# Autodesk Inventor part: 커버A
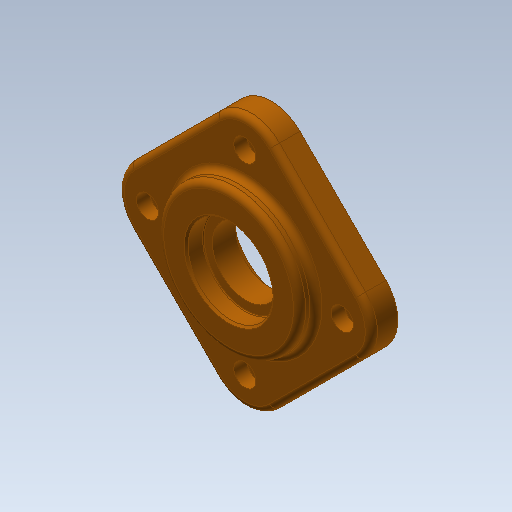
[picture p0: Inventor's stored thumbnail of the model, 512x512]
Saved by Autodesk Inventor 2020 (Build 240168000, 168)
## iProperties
Created: 2013-01
Part Number: 커버A
Document SubType Name: Modeling
Density: 1 g/cm^3
Material: 알루미늄 6061
Designer: mdu
Appearance: 주황색
Author: mdu
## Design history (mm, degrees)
sketch "스케치1"
  geometry: L1 (56.569, -14.142)-(14.142, -56.569) reference; L2 (-14.142, -56.569)-(-56.569, -14.142) reference; L3 (-56.569, 14.142)-(-14.142, 56.569) reference; L4 (14.142, 56.569)-(56.569, 14.142) reference; C1 r 31 at (0, 0) reference; A1 r 20 centre (0, -42.426) between (-14.142, -56.569) and (14.142, -56.569) reference; A2 r 20 centre (-42.426, 0) between (-56.569, 14.142) and (-56.569, -14.142) reference; A3 r 20 centre (0, 42.426) between (14.142, 56.569) and (-14.142, 56.569) reference; A4 r 20 centre (42.426, 0) between (56.569, -14.142) and (56.569, 14.142) reference; 1 further point
extrude "돌출1" new body sketch "스케치1" distance "d0" = 13; taper "d1" = 0 deg
sketch "스케치2"
  geometry: C1 r 35 at (0, 0); 1 further point
  constraints: 1 centre point, 1 coincident
  dimensions: "d2" = 70 diameter of C1
extrude "돌출2" join sketch "스케치2" distance "d3" = 8; taper "d4" = 0 deg
fillet "모깎기1" dims "d5" = 3
sketch "스케치3"
  geometry: C1 r 2.458 at (0, 48) reference; 1 further point
hole "구멍1" sketch "스케치3" at (0, 48) diameter "d6" = 6.6; stored, may be unused: countersink angle "d10" = 90 deg, drill point angle "d12" = 118 deg; dims "d7" = 6, "d8" = 11, "d9" = 6.5, "d11" = 8
hole "구멍2" diameter "d18" = 33; stored, may be unused: countersink angle "d22" = 90 deg, drill point angle "d24" = 118 deg; dims "d16" = 10, "d17" = 10, "d19" = 6, "d20" = 42, "d21" = 8.5, "d23" = 8
sketch "스케치4"
  geometry: C1 r 31 at (0, 0) reference; 1 further point
extrude "돌출3" join sketch "스케치4" distance "d25" = 6; taper "d26" = 0 deg
hole "구멍3" diameter "d29" = 50; stored, may be unused: countersink angle "d33" = 90 deg, drill point angle "d35" = 0 deg; dims "d27" = 10, "d28" = 10, "d30" = 6, "d31" = 42, "d32" = 8.5, "d34" = 7
fillet "모깎기2" dims "d36" = 3, "d37" = 0.4
chamfer "모따기1" distance "d38" = 1; stored, may be unused: second distance "d39" = 2, angle "d40" = 45 deg
node "솔리드1"
pattern_circular "원형 패턴1" dims angle "d14" = 360 deg
node "참조1"
node "참조2"
node "참조3"
node "참조4"
node "참조5"
node "참조6"
node "참조7"
node "참조8"
node "참조9"
node "참조10"
node "참조11"
